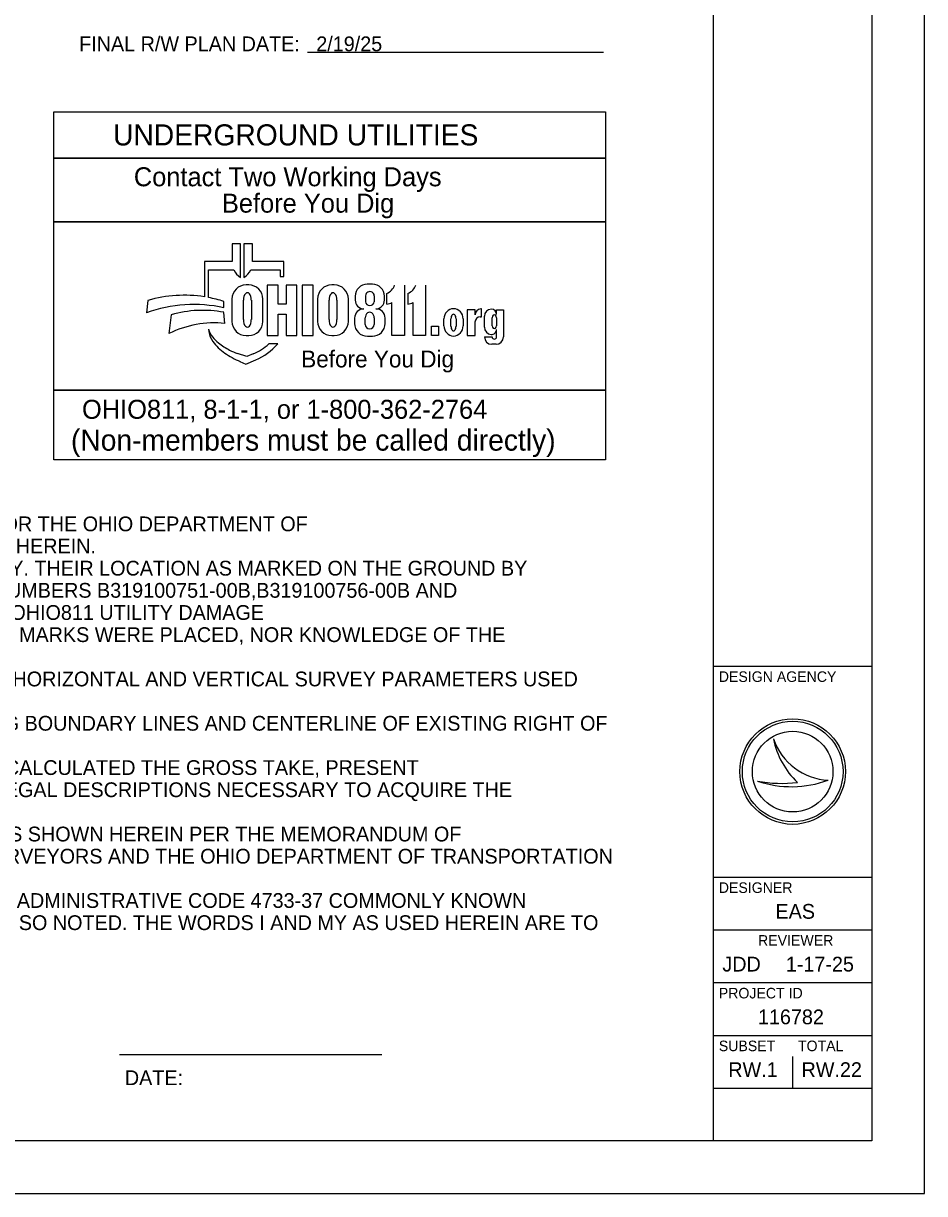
# Model space of a CAD drawing. Extents: x 0 to 34, y 0 to 22.
# Drawn here: x 25.46 to 34, y 0 to 11.09 of the extents above; entities that cross this region are included whole.
import ezdxf

# ---------------------------------------------------------------- set-up
doc = ezdxf.new("R2010")
doc.units = 0
for name, color, linetype in [('Default', 7, 'Continuous'), ('SH_Border', 7, 'Continuous'), ('SH_Cut_Line', 7, 'Continuous'), ('SH_Data', 7, 'Continuous'), ('SH_Text', 7, 'Continuous')]:
    doc.layers.add(name, color=color, linetype=linetype)

msp = doc.modelspace()

# ---------------------------------------------------------------- linework, layer by layer
at = {"layer": 'Default'}
msp.add_line((26.37, 1.318), (28.856, 1.318), dxfattribs=at)
at = {"layer": 'SH_Border'}
for p, q in [((32, 0.5), (32, 21.5)), ((32, 5), (33.5, 5)), ((32, 3), (33.5, 3)), ((32, 2.5), (33.5, 2.5)), ((32, 2), (33.5, 2)), ((32, 1.5), (33.5, 1.5)), ((32, 1), (33.5, 1))]:
    msp.add_line(p, q, dxfattribs=at)
msp.add_lwpolyline([(1.5, 21.5), (33.5, 21.5), (33.5, 0.5), (1.5, 0.5)], close=True, dxfattribs=at)
at = {"layer": 'SH_Cut_Line'}
msp.add_lwpolyline([(0, 0), (34, 0), (34, 22), (0, 22)], close=True, dxfattribs=at)
at = {"layer": 'SH_Data'}
for p, q in [((27.519, 9.001), (27.439, 9.001)), ((27.439, 9.001), (27.439, 8.834)), ((27.519, 8.684), (27.519, 9.001)), ((27.63, 9.001), (27.55, 9.001)), ((27.55, 9.001), (27.55, 8.684)), ((27.63, 8.834), (27.63, 9.001)), ((27.439, 8.834), (27.176, 8.834)), ((27.176, 8.834), (27.176, 8.5)), ((27.928, 8.834), (27.63, 8.834)), ((27.928, 8.694), (27.928, 8.834)), ((27.214, 8.493), (27.214, 8.757)), ((27.214, 8.757), (27.454, 8.757)), ((27.615, 8.757), (27.893, 8.757)), ((27.893, 8.757), (27.893, 8.694)), ((27.893, 8.694), (27.928, 8.694)), ((27.596, 8.613), (27.571, 8.613)), ((27.874, 8.612), (27.772, 8.612)), ((27.772, 8.612), (27.772, 8.134)), ((28.406, 8.613), (28.382, 8.613)), ((28.768, 8.62), (28.719, 8.62)), ((29.071, 8.612), (29.071, 8.134)), ((29.271, 8.612), (29.271, 8.134)), ((26.641, 8.466), (26.627, 8.349)), ((27.36, 8.398), (27.36, 8.456)), ((27.437, 8.479), (27.437, 8.267)), ((27.546, 8.284), (27.546, 8.467)), ((27.621, 8.467), (27.621, 8.284)), ((27.729, 8.267), (27.729, 8.479)), ((28.248, 8.479), (28.248, 8.267)), ((28.357, 8.284), (28.357, 8.467)), ((28.431, 8.467), (28.431, 8.284)), ((28.54, 8.267), (28.54, 8.479)), ((28.605, 8.506), (28.605, 8.469)), ((28.704, 8.452), (28.704, 8.511)), ((28.784, 8.511), (28.784, 8.452)), ((28.882, 8.469), (28.882, 8.506)), ((28.905, 8.431), (28.905, 8.533)), ((28.953, 8.134), (28.953, 8.445)), ((29.105, 8.431), (29.105, 8.533)), ((29.153, 8.134), (29.153, 8.445)), ((26.862, 8.33), (26.84, 8.151)), ((27.37, 8.247), (27.361, 8.353)), ((27.874, 8.134), (27.874, 8.336)), ((29.74, 8.377), (29.667, 8.377)), ((29.667, 8.377), (29.667, 8.134)), ((29.74, 8.33), (29.74, 8.377)), ((29.801, 8.385), (29.795, 8.385)), ((29.801, 8.31), (29.801, 8.385)), ((29.944, 8.332), (29.944, 8.378)), ((29.944, 8.378), (30.009, 8.378)), ((30.009, 8.378), (30.009, 8.12)), ((28.599, 8.299), (28.599, 8.248)), ((28.7, 8.239), (28.7, 8.301)), ((28.785, 8.301), (28.785, 8.239)), ((28.888, 8.248), (28.888, 8.299)), ((29.445, 8.224), (29.445, 8.292)), ((29.512, 8.223), (29.512, 8.292)), ((29.561, 8.292), (29.561, 8.223)), ((29.628, 8.292), (29.628, 8.224)), ((29.74, 8.134), (29.74, 8.261)), ((29.789, 8.31), (29.801, 8.31)), ((29.829, 8.212), (29.829, 8.316)), ((29.901, 8.226), (29.901, 8.302)), ((29.944, 8.302), (29.944, 8.226)), ((27.213, 8.194), (27.217, 8.167)), ((27.571, 8.134), (27.596, 8.134)), ((27.772, 8.134), (27.874, 8.134)), ((28.382, 8.134), (28.406, 8.134)), ((28.72, 8.127), (28.767, 8.127)), ((29.071, 8.134), (28.953, 8.134)), ((29.271, 8.134), (29.153, 8.134)), ((29.667, 8.134), (29.74, 8.134)), ((29.829, 8.12), (29.901, 8.12)), ((29.944, 8.12), (29.944, 8.189)), ((27.871, 8.054), (27.785, 8.054)), ((27.869, 8.051), (27.871, 8.054)), ((29.939, 8.05), (29.899, 8.05)), ((27.578, 7.933), (27.489, 7.963)), ((27.513, 7.887), (27.569, 7.863)), ((27.569, 7.863), (27.663, 7.904)), ((27.639, 7.959), (27.578, 7.933)), ((30.975, 6.955), (25.75, 6.955)), ((32.567, 4.31), (32.567, 4.31)), ((32.75, 4), (32.75, 4)), ((32.417, 3.91), (32.417, 3.91)), ((33.087, 3.919), (33.087, 3.919)), ((32.75, 1), (32.75, 1.3))]:
    msp.add_line(p, q, dxfattribs=at)
for points in [[(25.75, 10.255), (30.975, 10.255), (30.975, 9.815), (25.75, 9.815)], [(25.75, 9.815), (30.975, 9.815), (30.975, 9.21), (25.75, 9.21)], [(25.75, 9.21), (30.975, 9.21), (30.975, 7.615), (25.75, 7.615)], [(29.329, 8.223), (29.395, 8.223), (29.395, 8.134), (29.329, 8.134)], [(25.75, 7.615), (30.975, 7.615), (30.975, 6.955), (25.75, 6.955)]]:
    msp.add_lwpolyline(points, close=True, dxfattribs=at)
for points in [[(27.874, 8.336), (27.95, 8.336), (27.95, 8.134), (28.051, 8.134), (28.051, 8.612), (27.95, 8.612), (27.95, 8.431), (27.874, 8.431), (27.874, 8.612)], [(28.102, 8.134), (28.205, 8.134), (28.205, 8.612), (28.102, 8.612), (28.102, 8.134)], [(28.686, 8.386), (28.686, 8.386)], [(28.801, 8.386), (28.801, 8.386)]]:
    msp.add_lwpolyline(points, dxfattribs=at)
for radius in [0.5, 0.477, 0.477, 0.382]:
    msp.add_circle((32.75, 4), radius, dxfattribs=at)
for centre, radius, start, end in [((27.591, 8.812), 0.147, 201.9296, 240.7469), ((27.478, 8.812), 0.147, 299.2531, 338.0704), ((27.571, 8.479), 0.134, 90, 180), ((27.596, 8.479), 0.134, 0, 90), ((28.382, 8.479), 0.134, 90, 180), ((28.406, 8.479), 0.134, 0, 90), ((28.719, 8.506), 0.114, 90, 180), ((28.768, 8.506), 0.114, 0, 90), ((28.854, 8.655), 0.132, 292.5572, 340.7355), ((29.054, 8.655), 0.132, 292.5572, 340.7355), ((26.985, 7.291), 1.224, 81.0007, 106.3144), ((26.985, 7.291), 1.224, 72.1402, 79.2074), ((28.688, 8.469), 0.0837, 180, 268.1442), ((28.798, 8.469), 0.0837, 272.2058, 0), ((28.893, 8.563), 0.132, 275.1733, 297.0931), ((29.093, 8.563), 0.132, 275.1733, 297.0931), ((27.079, 7.095), 1.332, 77.8238, 109.8274), ((27.16, 7.278), 1.094, 79.44, 105.8467), ((28.686, 8.299), 0.0865, 90, 180), ((28.801, 8.299), 0.0865, 0, 90), ((29.541, 8.292), 0.0956, 92.5886, 180), ((29.532, 8.292), 0.0956, 0, 87.4114), ((29.795, 8.33), 0.0548, 90, 180), ((29.898, 8.316), 0.0686, 92.6865, 180), ((29.892, 8.332), 0.0524, 0, 86.9262), ((27.268, 7.303), 0.95, 83.8248, 116.8021), ((27.571, 8.267), 0.134, 180, 270), ((27.596, 8.267), 0.134, 270, 0), ((28.382, 8.267), 0.134, 180, 270), ((28.406, 8.267), 0.134, 270, 0), ((28.72, 8.248), 0.121, 180, 270), ((28.767, 8.248), 0.121, 270, 0), ((29.541, 8.224), 0.0956, 180, 267.4114), ((29.532, 8.224), 0.0956, 272.5886, 0), ((29.789, 8.261), 0.0493, 90, 180), ((29.898, 8.212), 0.0692, 180, 265.7132), ((27.493, 8.301), 0.3, 201.0457, 232.5314), ((27.428, 8.203), 0.214, 189.6817, 216.0884), ((29.899, 8.12), 0.0699, 180, 270), ((29.897, 8.189), 0.0467, 264.7825, 0), ((29.939, 8.12), 0.0699, 270, 0), ((27.628, 8.348), 0.461, 216.0884, 235.7167), ((27.78, 8.677), 0.773, 232.5314, 241.794), ((27.653, 8.439), 0.504, 241.794, 250.9821), ((27.425, 8.453), 0.538, 293.4582, 312.0712), ((27.425, 8.453), 0.599, 293.4582, 317.8286), ((27.877, 8.713), 0.903, 235.7167, 246.2325), ((33.116, 4.498), 0.58, 198.9257, 198.9319), ((33.347, 4.47), 0.796, 191.6379, 191.6421), ((33.116, 4.498), 0.58, 198.9319, 267.1657), ((33.347, 4.47), 0.796, 191.6421, 226.0947), ((32.739, 4.87), 1.013, 251.4576, 290.0832), ((32.648, 5.154), 1.266, 259.4964, 259.4995), ((32.739, 4.87), 1.013, 251.4527, 251.4576), ((32.648, 5.154), 1.266, 259.4995, 276.6672)]:
    msp.add_arc(centre, radius, start, end, dxfattribs=at)
for centre, major_axis, ratio, start_param, end_param in [((28.744, 8.511), (0.0404, 0), 0.969373, 0, 3.141593), ((27.583, 8.467), (0, 0.0723), 0.514403, 4.712389, 7.853982), ((28.394, 8.467), (0, 0.0723), 0.514403, 4.712389, 7.853982), ((28.744, 8.452), (0.0404, 0), 0.818453, 3.141593, 6.283185), ((28.742, 8.301), (0, 0.0535), 0.794529, 4.712389, 7.853982), ((29.536, 8.292), (0, 0.0434), 0.553236, 4.712389, 7.853982), ((29.923, 8.302), (0, 0.0275), 0.777179, 4.712389, 7.853982), ((27.583, 8.284), (0, 0.0723), 0.514403, 1.570796, 4.712389), ((28.394, 8.284), (0, 0.0723), 0.514403, 1.570796, 4.712389), ((28.742, 8.239), (0.0425, 0), 0.959837, 3.141593, 6.283185), ((29.536, 8.223), (0, 0.046), 0.522014, 1.570796, 4.712389), ((29.923, 8.226), (0, 0.0275), 0.777179, 1.570796, 4.712389), ((29.923, 8.12), (0.0214, 0), 0.959012, 3.141593, 6.283185)]:
    msp.add_ellipse(centre, major_axis=major_axis, ratio=ratio, start_param=start_param, end_param=end_param, dxfattribs=at)
at = {"layer": 'SH_Text'}
msp.add_line((28.154, 10.818), (30.958, 10.818), dxfattribs=at)

# ---------------------------------------------------------------- texts
at = {"layer": 'Default'}
for s, p in [('I, JAMIE D. DARR, P.S. HAVE CONDUCTED A SURVEY OF THE EXISTING CONDITIONS FOR THE OHIO DEPARTMENT OF', (17.41, 6.278)), ('TRANSPORTATION IN AUGUST 2023. THE RESULTS OF THAT SURVEY ARE CONTAINED HEREIN.', (17.41, 6.068)), ('UNDERGROUND UTILITY LOCATIONS ARE SHOWN FOR INFORMATION PURPOSES ONLY. THEIR LOCATION AS MARKED ON THE GROUND BY ', (17.41, 5.858)), ('THE UTILITY COMPANY OR THEIR REPRESENTATIVES PER OHIO811 CONFIRMATION NUMBERS B319100751-00B,B319100756-00B AND', (17.41, 5.648)), ('B319100742 WERE SURVEYED AND MAPPED AS PART OF THIS PROJECT. I FOLLOWED OHIO811 UTILITY DAMAGE', (17.41, 5.438)), ('PREVENTION LAWS AND HAVE NO DIRECT KNOWLEDGE OR CONTROL OF HOW THESE MARKS WERE PLACED, NOR KNOWLEDGE OF THE ', (17.41, 5.228)), ('SEE THE AFFIXED SURVEY PARAMETERS NOTE ON THE CENTERLINE PLATS FOR THE HORIZONTAL AND VERTICAL SURVEY PARAMETERS USED ', (17.41, 4.808)), ('AS PART OF THIS PROJECT I HAVE REESTABLISHED THE LOCATIONS OF THE EXISTING BOUNDARY LINES AND CENTERLINE OF EXISTING RIGHT OF ', (17.41, 4.388)), ('AS PART OF THIS PROJECT I HAVE ESTABLISHED THE PROPOSED BOUNDARY LINES, CALCULATED THE GROSS TAKE, PRESENT', (17.41, 3.968)), ('ROAD OCCUPIED (PRO), NET TAKE, AND NET RESIDUE; AS WELL AS PREPARED THE LEGAL DESCRIPTIONS NECESSARY TO ACQUIRE THE', (17.41, 3.758)), ('AS PART OF THIS WORK, RIGHT OF WAY MONUMENTS WILL BE SET AT THE LOCATIONS SHOWN HEREIN PER THE MEMORANDUM OF ', (17.41, 3.338)), ('UNDERSTANDING BETWEEN THE BOARD OF REGISTRATION FOR ENGINEERS AND SURVEYORS AND THE OHIO DEPARTMENT OF TRANSPORTATION ', (17.41, 3.128)), ('ALL OF MY WORK CONTAINED HEREIN WAS CONDUCTED IN ACCORDANCE WITH OHIO ADMINISTRATIVE CODE 4733-37 COMMONLY KNOWN', (17.41, 2.708)), ('AS "MINIMUM STANDARDS FOR BOUNDARY SURVEYS IN THE STATE OF OHIO" UNLESS SO NOTED. THE WORDS I AND MY AS USED HEREIN ARE TO', (17.41, 2.498)), (' DATE:', (26.37, 1.028))]:
    msp.add_text(s, height=0.14, dxfattribs=at).set_placement(p)
at = {"layer": 'SH_Data'}
for s, height, p in [('UNDERGROUND UTILITIES', 0.2, (26.31, 9.935)), ('Contact Two Working Days', 0.18, (26.507, 9.548)), ('Before You Dig', 0.18, (27.342, 9.298)), ('Before You Dig', 0.15972, (28.093, 7.831)), ('OHIO811, 8-1-1, or 1-800-362-2764', 0.18, (26.016, 7.344)), ('(Non-members must be called directly)', 0.2, (25.911, 7.042)), ('DESIGN AGENCY', 0.1, (32.05, 4.85)), ('DESIGNER', 0.1, (32.05, 2.85)), ('EAS', 0.14, (32.587, 2.605)), ('REVIEWER', 0.1, (32.422, 2.35)), ('JDD', 0.14, (32.084, 2.105)), ('1-17-25', 0.14, (32.685, 2.105)), ('PROJECT ID', 0.1, (32.05, 1.85)), ('116782', 0.14, (32.421, 1.605)), ('SUBSET', 0.1, (32.05, 1.35)), ('TOTAL', 0.1, (32.8, 1.35)), ('RW.1', 0.14, (32.14, 1.105)), ('RW.22', 0.14, (32.834, 1.105))]:
    msp.add_text(s, height=height, dxfattribs=at).set_placement(p)
at = {"layer": 'SH_Text'}
msp.add_text('FINAL R/W PLAN DATE:   2/19/25', height=0.14, dxfattribs=at).set_placement((25.989, 10.828))

doc.saveas('drawing.dxf')
